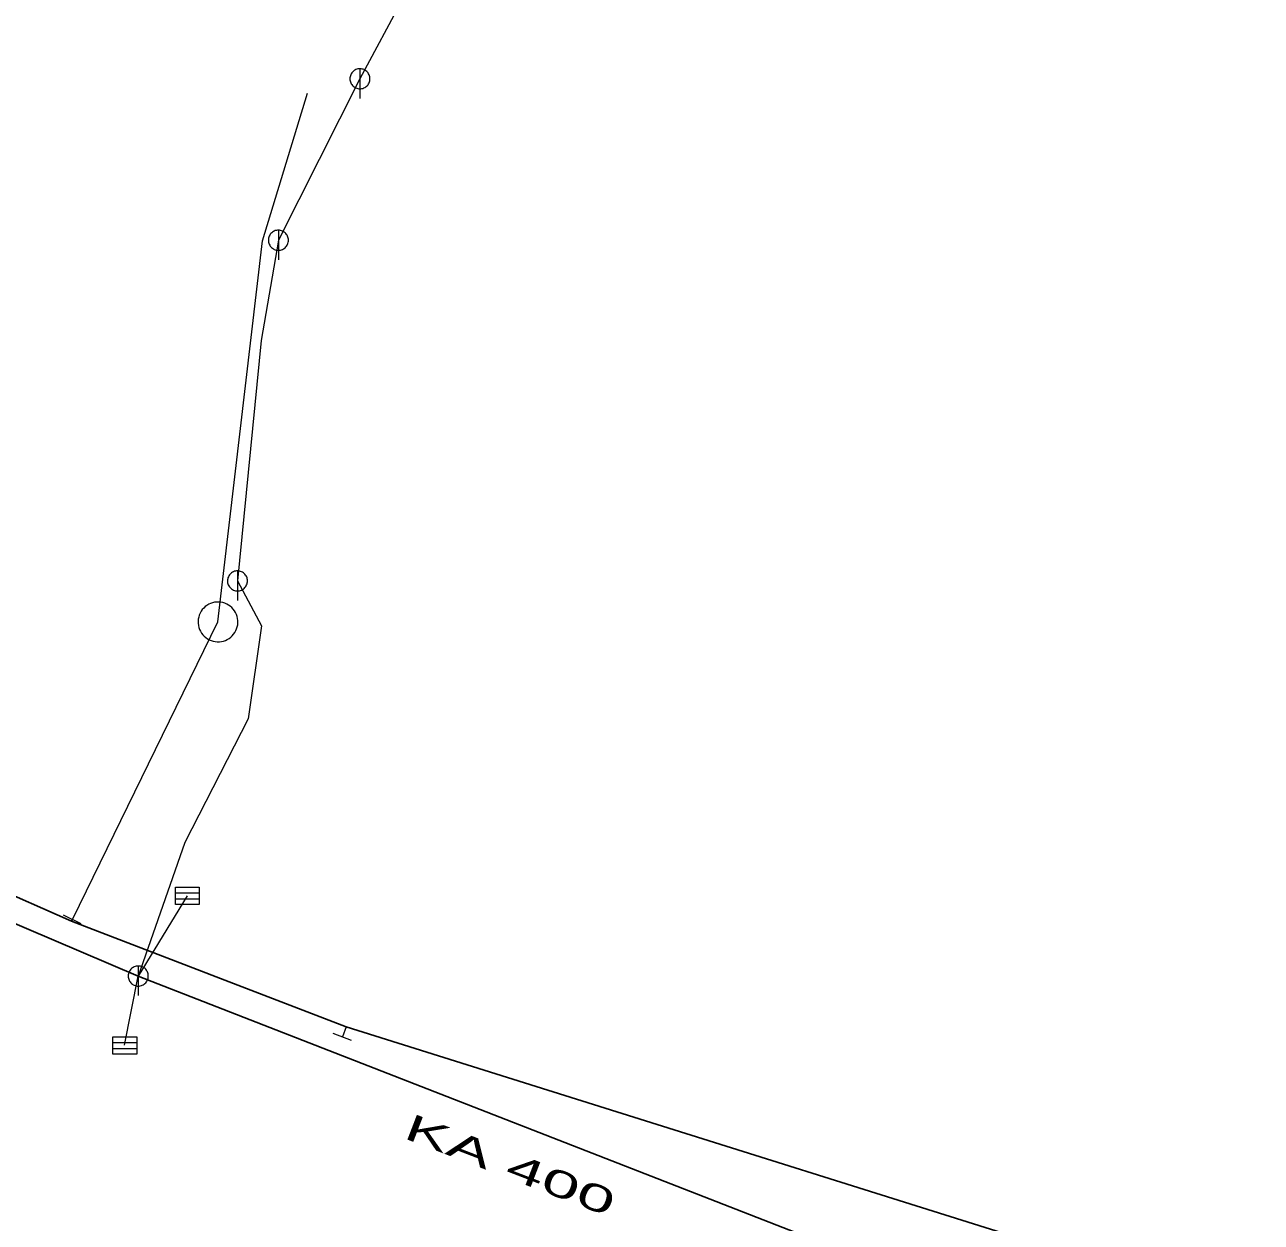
# Model space of a CAD drawing. Extents: x -687468 to -685917, y -974192 to -973456.
# Drawn here: x -686537.42 to -686506.35, y -973715.44 to -973685.34 of the extents above; entities that cross this region are included whole.
import ezdxf
from ezdxf.enums import TextEntityAlignment as Align

# ---------------------------------------------------------------- set-up
doc = ezdxf.new("R2010")
doc.units = 0
doc.header["$LTSCALE"] = 0.27
for name, color, linetype, lineweight in [('1', 7, 'Continuous', 13), ('11', 7, 'Continuous', 13), ('13', 7, 'Continuous', 13), ('14', 7, 'Continuous', 25), ('17', 7, 'Continuous', 25), ('22', 7, 'Continuous', 13), ('23', 7, 'Continuous', 13), ('34', 7, 'Continuous', 13)]:
    doc.layers.add(name, color=color, linetype=linetype, lineweight=lineweight)

msp = doc.modelspace()

# ---------------------------------------------------------------- linework, layer by layer
at = {"layer": '11'}
for p, q in [((-686524.329, -973678), (-686528.997, -973686.699)), ((-686528.997, -973686.699), (-686531.046, -973690.756)), ((-686533.34, -973707.23), (-686534.568, -973709.248)), ((-686534.91, -973710.989), (-686534.568, -973709.248))]:
    msp.add_line(p, q, dxfattribs=at)
for points in [[(-686531.046, -973690.756), (-686531.478, -973693.278), (-686532.074, -973699.317)], [(-686532.074, -973699.317), (-686531.469, -973700.447), (-686531.805, -973702.787), (-686533.401, -973705.888), (-686534.568, -973709.248)]]:
    msp.add_lwpolyline(points, dxfattribs=at)
at = {"layer": '13'}
msp.add_line((-686536.224, -973707.826), (-686532.565, -973700.348), dxfattribs=at)
msp.add_lwpolyline([(-686532.565, -973700.348), (-686531.445, -973690.774), (-686530.313, -973687.056)], dxfattribs=at)
at = {"layer": '14'}
for p, q in [((-686534.568, -973709.248), (-686555.059, -973700.55)), ((-686515.17, -973716.809), (-686534.568, -973709.248))]:
    msp.add_line(p, q, dxfattribs=at)
at = {"layer": '14', "lineweight": 13}
for p, q in [((-686536.247, -973707.872), (-686536.224, -973707.826)), ((-686529.344, -973710.524), (-686529.439, -973710.779))]:
    msp.add_line(p, q, dxfattribs=at)
at = {"layer": '17'}
msp.add_lwpolyline([(-686506.346, -973717.746), (-686529.344, -973710.524), (-686536.247, -973707.872), (-686555.026, -973699.577), (-686572.978, -973698.129), (-686583.112, -973698.418), (-686615.962, -973695.359), (-686637.993, -973681.581), (-686653.818, -973675.34), (-686693.532, -973676.405), (-686696.345, -973676.48)], dxfattribs=at)
at = {"layer": '22'}
for p, q in [((-686528.996, -973686.447), (-686528.997, -973687.191)), ((-686531.045, -973690.504), (-686531.046, -973691.248)), ((-686532.073, -973699.065), (-686532.074, -973699.809)), ((-686533.635, -973707.159), (-686533.037, -973707.159)), ((-686533.635, -973707.304), (-686533.037, -973707.304)), ((-686534.567, -973708.996), (-686534.568, -973709.74)), ((-686535.205, -973710.919), (-686534.607, -973710.919)), ((-686535.205, -973711.065), (-686534.607, -973711.065))]:
    msp.add_line(p, q, dxfattribs=at)
for points in [[(-686528.745, -973686.699), (-686528.746, -973686.673), (-686528.75, -973686.647), (-686528.756, -973686.621), (-686528.766, -973686.597), (-686528.778, -973686.573), (-686528.792, -973686.551), (-686528.809, -973686.53), (-686528.827, -973686.512), (-686528.848, -973686.495), (-686528.87, -973686.481), (-686528.894, -973686.469), (-686528.918, -973686.459), (-686528.944, -973686.453), (-686528.97, -973686.449), (-686528.996, -973686.447), (-686529.022, -973686.448), (-686529.048, -973686.452), (-686529.074, -973686.458), (-686529.099, -973686.468), (-686529.122, -973686.48), (-686529.144, -973686.494), (-686529.165, -973686.511), (-686529.183, -973686.529), (-686529.2, -973686.55), (-686529.214, -973686.572), (-686529.226, -973686.596), (-686529.236, -973686.62), (-686529.243, -973686.646), (-686529.247, -973686.672), (-686529.249, -973686.698), (-686529.248, -973686.724), (-686529.244, -973686.75), (-686529.237, -973686.776), (-686529.227, -973686.801), (-686529.215, -973686.824), (-686529.201, -973686.846), (-686529.184, -973686.867), (-686529.166, -973686.885), (-686529.145, -973686.902), (-686529.123, -973686.916), (-686529.1, -973686.928), (-686529.075, -973686.938), (-686529.049, -973686.945), (-686529.023, -973686.949), (-686528.997, -973686.951), (-686528.971, -973686.95), (-686528.945, -973686.946), (-686528.919, -973686.939), (-686528.895, -973686.929), (-686528.871, -973686.917), (-686528.849, -973686.903), (-686528.828, -973686.886), (-686528.81, -973686.868), (-686528.793, -973686.847), (-686528.779, -973686.825), (-686528.767, -973686.802), (-686528.757, -973686.777), (-686528.751, -973686.751), (-686528.747, -973686.725)], [(-686530.794, -973690.756), (-686530.795, -973690.73), (-686530.799, -973690.704), (-686530.805, -973690.678), (-686530.815, -973690.654), (-686530.827, -973690.63), (-686530.841, -973690.608), (-686530.858, -973690.587), (-686530.876, -973690.569), (-686530.897, -973690.552), (-686530.919, -973690.538), (-686530.943, -973690.526), (-686530.967, -973690.516), (-686530.993, -973690.51), (-686531.019, -973690.506), (-686531.045, -973690.504), (-686531.071, -973690.505), (-686531.097, -973690.509), (-686531.123, -973690.515), (-686531.148, -973690.525), (-686531.171, -973690.537), (-686531.193, -973690.551), (-686531.214, -973690.568), (-686531.232, -973690.586), (-686531.249, -973690.607), (-686531.263, -973690.629), (-686531.275, -973690.653), (-686531.285, -973690.677), (-686531.292, -973690.703), (-686531.296, -973690.729), (-686531.298, -973690.755), (-686531.297, -973690.781), (-686531.293, -973690.807), (-686531.286, -973690.833), (-686531.276, -973690.858), (-686531.264, -973690.881), (-686531.25, -973690.903), (-686531.233, -973690.924), (-686531.215, -973690.942), (-686531.194, -973690.959), (-686531.172, -973690.973), (-686531.149, -973690.985), (-686531.124, -973690.995), (-686531.098, -973691.002), (-686531.072, -973691.006), (-686531.046, -973691.008), (-686531.02, -973691.007), (-686530.994, -973691.003), (-686530.968, -973690.996), (-686530.944, -973690.986), (-686530.92, -973690.974), (-686530.898, -973690.96), (-686530.877, -973690.943), (-686530.859, -973690.925), (-686530.842, -973690.904), (-686530.828, -973690.882), (-686530.816, -973690.859), (-686530.806, -973690.834), (-686530.8, -973690.808), (-686530.796, -973690.782)], [(-686531.822, -973699.317), (-686531.823, -973699.291), (-686531.827, -973699.265), (-686531.833, -973699.239), (-686531.843, -973699.215), (-686531.855, -973699.191), (-686531.869, -973699.169), (-686531.886, -973699.148), (-686531.904, -973699.13), (-686531.925, -973699.113), (-686531.947, -973699.099), (-686531.971, -973699.087), (-686531.995, -973699.077), (-686532.021, -973699.071), (-686532.047, -973699.067), (-686532.073, -973699.065), (-686532.099, -973699.066), (-686532.125, -973699.07), (-686532.151, -973699.076), (-686532.176, -973699.086), (-686532.199, -973699.098), (-686532.221, -973699.112), (-686532.242, -973699.129), (-686532.26, -973699.147), (-686532.277, -973699.168), (-686532.291, -973699.19), (-686532.303, -973699.214), (-686532.313, -973699.238), (-686532.32, -973699.264), (-686532.324, -973699.29), (-686532.326, -973699.316), (-686532.325, -973699.342), (-686532.321, -973699.368), (-686532.314, -973699.394), (-686532.304, -973699.419), (-686532.292, -973699.442), (-686532.278, -973699.464), (-686532.261, -973699.485), (-686532.243, -973699.503), (-686532.222, -973699.52), (-686532.2, -973699.534), (-686532.177, -973699.546), (-686532.152, -973699.556), (-686532.126, -973699.563), (-686532.1, -973699.567), (-686532.074, -973699.569), (-686532.048, -973699.568), (-686532.022, -973699.564), (-686531.996, -973699.557), (-686531.972, -973699.547), (-686531.948, -973699.535), (-686531.926, -973699.521), (-686531.905, -973699.504), (-686531.887, -973699.486), (-686531.87, -973699.465), (-686531.856, -973699.443), (-686531.844, -973699.42), (-686531.834, -973699.395), (-686531.828, -973699.369), (-686531.824, -973699.343)], [(-686533.635, -973707.013), (-686533.037, -973707.013), (-686533.037, -973707.45), (-686533.635, -973707.45)], [(-686534.316, -973709.248), (-686534.317, -973709.222), (-686534.321, -973709.196), (-686534.327, -973709.17), (-686534.337, -973709.146), (-686534.349, -973709.122), (-686534.363, -973709.1), (-686534.38, -973709.079), (-686534.398, -973709.061), (-686534.419, -973709.044), (-686534.441, -973709.03), (-686534.465, -973709.018), (-686534.489, -973709.008), (-686534.515, -973709.002), (-686534.541, -973708.998), (-686534.567, -973708.996), (-686534.593, -973708.997), (-686534.619, -973709.001), (-686534.645, -973709.007), (-686534.67, -973709.017), (-686534.693, -973709.029), (-686534.715, -973709.043), (-686534.736, -973709.06), (-686534.754, -973709.078), (-686534.771, -973709.099), (-686534.785, -973709.121), (-686534.797, -973709.145), (-686534.807, -973709.169), (-686534.814, -973709.195), (-686534.818, -973709.221), (-686534.82, -973709.247), (-686534.819, -973709.273), (-686534.815, -973709.299), (-686534.808, -973709.325), (-686534.798, -973709.35), (-686534.786, -973709.373), (-686534.772, -973709.395), (-686534.755, -973709.416), (-686534.737, -973709.434), (-686534.716, -973709.451), (-686534.694, -973709.465), (-686534.671, -973709.477), (-686534.646, -973709.487), (-686534.62, -973709.494), (-686534.594, -973709.498), (-686534.568, -973709.5), (-686534.542, -973709.499), (-686534.516, -973709.495), (-686534.49, -973709.488), (-686534.466, -973709.478), (-686534.442, -973709.466), (-686534.42, -973709.452), (-686534.399, -973709.435), (-686534.381, -973709.417), (-686534.364, -973709.396), (-686534.35, -973709.374), (-686534.338, -973709.351), (-686534.328, -973709.326), (-686534.322, -973709.3), (-686534.318, -973709.274)], [(-686535.205, -973710.773), (-686534.607, -973710.773), (-686534.607, -973711.21), (-686535.205, -973711.21)]]:
    msp.add_lwpolyline(points, close=True, dxfattribs=at)
at = {"layer": '23'}
msp.add_lwpolyline([(-686532.345, -973699.898), (-686532.393, -973699.878), (-686532.443, -973699.863), (-686532.494, -973699.853), (-686532.546, -973699.848), (-686532.599, -973699.849), (-686532.651, -973699.855), (-686532.701, -973699.867), (-686532.751, -973699.884), (-686532.798, -973699.906), (-686532.844, -973699.933), (-686532.886, -973699.964), (-686532.923, -973700), (-686532.958, -973700.039), (-686532.988, -973700.082), (-686533.014, -973700.128), (-686533.034, -973700.176), (-686533.049, -973700.226), (-686533.059, -973700.278), (-686533.064, -973700.329), (-686533.063, -973700.382), (-686533.057, -973700.434), (-686533.045, -973700.485), (-686533.028, -973700.535), (-686533.007, -973700.582), (-686532.979, -973700.627), (-686532.948, -973700.669), (-686532.912, -973700.707), (-686532.873, -973700.741), (-686532.83, -973700.771), (-686532.784, -973700.797), (-686532.736, -973700.817), (-686532.686, -973700.832), (-686532.635, -973700.843), (-686532.583, -973700.847), (-686532.53, -973700.846), (-686532.478, -973700.841), (-686532.427, -973700.829), (-686532.378, -973700.812), (-686532.33, -973700.79), (-686532.285, -973700.762), (-686532.243, -973700.731), (-686532.205, -973700.696), (-686532.171, -973700.656), (-686532.141, -973700.613), (-686532.115, -973700.567), (-686532.095, -973700.519), (-686532.08, -973700.469), (-686532.069, -973700.418), (-686532.065, -973700.366), (-686532.066, -973700.313), (-686532.071, -973700.261), (-686532.084, -973700.211), (-686532.101, -973700.162), (-686532.123, -973700.114), (-686532.15, -973700.068), (-686532.181, -973700.026), (-686532.216, -973699.989), (-686532.256, -973699.954), (-686532.299, -973699.924)], close=True, dxfattribs=at)
at = {"layer": '34'}
for p, q in [((-686536.001, -973707.934), (-686536.446, -973707.717)), ((-686529.206, -973710.866), (-686529.671, -973710.691))]:
    msp.add_line(p, q, dxfattribs=at)

# ---------------------------------------------------------------- texts
at = {"layer": '1', "width": 1.9}
msp.add_text('KA 400', height=0.6667, rotation=339, dxfattribs=at).set_placement((-686525.34, -973714.304), align=Align.CENTER)

doc.saveas('drawing.dxf')
